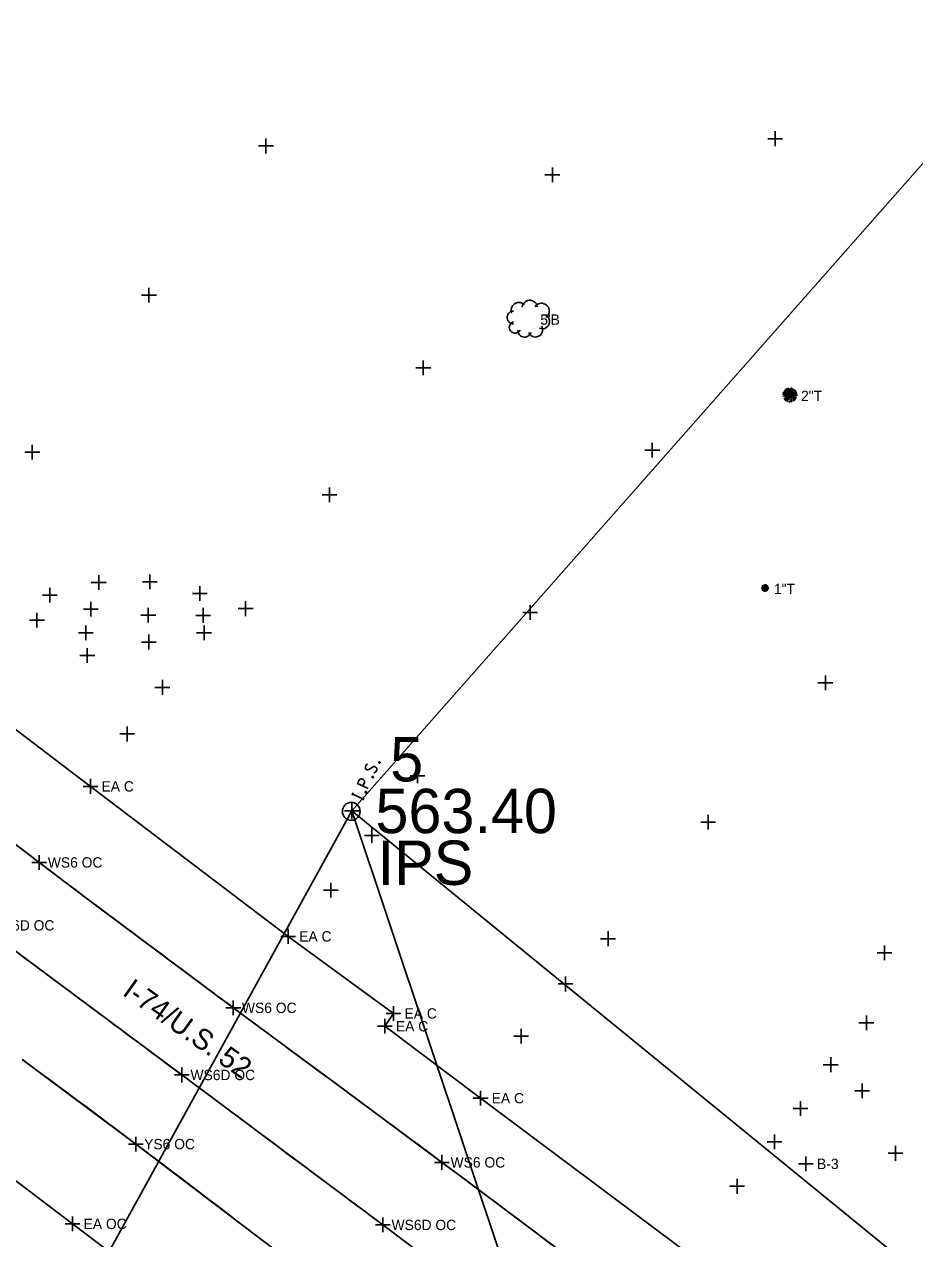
# Model space of a CAD drawing. Extents: x 1324236 to 1326110, y 459090 to 460782.
# Drawn here: x 1325040 to 1325160.4, y 460139.7 to 460303.9 of the extents above; entities that cross this region are included whole.
import ezdxf

# ---------------------------------------------------------------- set-up
doc = ezdxf.new("R2010")
doc.units = 0
for name, color, linetype in [('BD_X_Canopy', 7, 'Continuous'), ('DR_X_Ditch', 7, 'Continuous'), ('DT_X_Contour_Major', 7, 'Continuous'), ('DV_X_Property_Line', 7, 'Continuous'), ('E-RW-ODOT', 7, 'Continuous'), ('PM_X_Edge_Line', 7, 'Continuous'), ('PM_X_Lane_Line', 7, 'Continuous'), ('PV_X_Shoulder', 7, 'Continuous'), ('RD_X_Text', 7, 'Continuous'), ('RW_X_CL', 7, 'Continuous'), ('VG_X_Cells', 7, 'Continuous')]:
    doc.layers.add(name, color=color, linetype=linetype)

msp = doc.modelspace()

# ---------------------------------------------------------------- linework, layer by layer
at = {"layer": 'BD_X_Canopy'}
msp.add_lwpolyline([(1325148.74, 460096.82), (1325127.48, 460112.15), (1325127.48, 460112.15), (1325116.07, 460120.63), (1325116.07, 460120.63), (1325091.58, 460139.19), (1325091.58, 460139.19), (1325088.48, 460141.52), (1325088.48, 460141.52), (1325074.63, 460151.85), (1325074.63, 460151.85), (1325061.29, 460161.8), (1325061.29, 460161.8), (1325040.71, 460177.13), (1325040.71, 460177.13), (1325034.15, 460182.03)], dxfattribs=at)
at = {"layer": 'DR_X_Ditch'}
for points in [[(1325155.49, 460106.11), (1325134.69, 460121.41), (1325134.69, 460121.41), (1325123.41, 460129.81), (1325123.41, 460129.81), (1325098.92, 460148.15), (1325098.92, 460148.15), (1325096.46, 460149.98), (1325096.46, 460149.98), (1325083.31, 460159.73), (1325083.31, 460159.73), (1325068.25, 460170.88), (1325068.25, 460170.88), (1325049.77, 460184.67), (1325049.77, 460184.67), (1325042.01, 460190.54), (1325042.01, 460190.54), (1325032.41, 460197.89)], [(1325154.47, 460078.07), (1325145.11, 460085.02), (1325145.11, 460085.02), (1325142.61, 460086.87), (1325142.61, 460086.87), (1325114.79, 460107.64), (1325114.79, 460107.64), (1325109.8, 460111.36), (1325109.8, 460111.36), (1325095.42, 460122.04), (1325095.42, 460122.04), (1325082.31, 460131.78), (1325082.31, 460131.78), (1325070.85, 460140.45), (1325070.85, 460140.45), (1325055.08, 460152.45), (1325055.08, 460152.45), (1325039.72, 460163.87)]]:
    msp.add_lwpolyline(points, dxfattribs=at)
at = {"layer": 'DT_X_Contour_Major'}
for points in [[(1325086.41, 460203.88), (1325086.38, 460203.87), (1325086.34, 460203.85), (1325086.26, 460203.78), (1325086.19, 460203.68), (1325086.15, 460203.6), (1325086.14, 460203.57), (1325086.11, 460203.42), (1325086.13, 460203.28), (1325086.19, 460203.17), (1325086.27, 460203.11), (1325086.34, 460203.08), (1325086.44, 460203.05), (1325086.56, 460203.1), (1325087.16, 460203.49), (1325087.22, 460203.52), (1325087.28, 460203.52), (1325087.36, 460203.51), (1325087.43, 460203.48), (1325087.49, 460203.43), (1325087.53, 460203.4), (1325087.58, 460203.36), (1325087.62, 460203.32), (1325087.64, 460203.28), (1325087.66, 460203.23), (1325087.67, 460203.19), (1325087.68, 460203.14), (1325087.67, 460203.11), (1325087.64, 460203.01), (1325087.58, 460202.87), (1325087.51, 460202.79), (1325087.37, 460202.7), (1325087.27, 460202.65)], [(1325087.9, 460204.09), (1325087.93, 460204.14), (1325087.96, 460204.16), (1325088.02, 460204.17), (1325088.08, 460204.14), (1325088.11, 460204.09), (1325088.12, 460204.05), (1325088.1, 460204), (1325088.06, 460203.98), (1325088, 460203.97), (1325087.95, 460204), (1325087.91, 460204.05), (1325087.9, 460204.09)], [(1325086.5, 460200.53), (1325085.05, 460201.2), (1325085.27, 460201.68), (1325085.3, 460201.72), (1325085.36, 460201.78), (1325085.39, 460201.8), (1325085.43, 460201.82), (1325085.51, 460201.83), (1325085.58, 460201.84), (1325085.68, 460201.82), (1325085.82, 460201.75), (1325085.86, 460201.72), (1325085.92, 460201.67), (1325085.98, 460201.59), (1325085.99, 460201.54), (1325086, 460201.5), (1325086, 460201.44), (1325085.98, 460201.35), (1325085.76, 460200.87)], [(1325086.99, 460202.11), (1325087.02, 460202.16), (1325087.05, 460202.18), (1325087.11, 460202.19), (1325087.17, 460202.16), (1325087.2, 460202.11), (1325087.21, 460202.07), (1325087.19, 460202.02), (1325087.15, 460202), (1325087.09, 460201.99), (1325087.03, 460202.02), (1325087, 460202.07), (1325086.99, 460202.11)], [(1325084.32, 460199.62), (1325084.47, 460199.94)], [(1325085.85, 460199.11), (1325084.39, 460199.78)], [(1325085.77, 460198.95), (1325085.92, 460199.27)], [(1325086.05, 460200.07), (1325086.08, 460200.12), (1325086.11, 460200.14), (1325086.17, 460200.15), (1325086.23, 460200.12), (1325086.26, 460200.07), (1325086.27, 460200.03), (1325086.25, 460199.98), (1325086.21, 460199.96), (1325086.15, 460199.95), (1325086.09, 460199.98), (1325086.06, 460200.03), (1325086.05, 460200.07)]]:
    msp.add_lwpolyline(points, dxfattribs=at)
msp.add_circle((1325084.2, 460197.45), 1.2, dxfattribs=at)
at = {"layer": 'DV_X_Property_Line'}
for p, q in [((1325048.93, 460199.83), (1325048.93, 460201.83)), ((1325047.93, 460200.83), (1325049.93, 460200.83)), ((1325074.66, 460180.54), (1325076.66, 460180.54)), ((1325075.66, 460179.54), (1325075.66, 460181.54)), ((1325089.9, 460169.12), (1325089.9, 460171.12)), ((1325088.74, 460167.39), (1325088.74, 460169.39)), ((1325088.9, 460170.12), (1325090.9, 460170.12)), ((1325087.74, 460168.39), (1325089.74, 460168.39)), ((1325101.69, 460157.66), (1325101.69, 460159.66)), ((1325100.69, 460158.66), (1325102.69, 460158.66)), ((1325045.51, 460141.66), (1325047.51, 460141.66)), ((1325046.51, 460140.66), (1325046.51, 460142.66))]:
    msp.add_line(p, q, dxfattribs=at)
at = {"layer": 'E-RW-ODOT'}
for p, q in [((1325084.27, 460197.5), (1325254.99, 460391.14)), ((1325006.97, 460057.15), (1325084.27, 460197.5)), ((1325083.27, 460197.5), (1325085.27, 460197.5)), ((1325084.27, 460196.5), (1325084.27, 460198.5)), ((1325273.55, 460043.16), (1325084.27, 460197.5)), ((1325084.27, 460197.5), (1325176.95, 459920.27)), ((1325176.95, 459920.27), (1325084.27, 460197.5))]:
    msp.add_line(p, q, dxfattribs=at)
at = {"layer": 'PM_X_Edge_Line'}
for centre, radius, start, end in [((1326997.41, 462756.67), 3226.24, 232.47772, 232.69234), ((1325757.31, 461129.25), 1180.18, 232.69234, 233.16494), ((1329019.86, 465484.83), 6622.17, 233.16494, 233.364453), ((1328027.47, 464150.31), 4959.11, 233.36445, 233.5809), ((1324002.76, 458753.67), 1750.42, 53.04545, 53.67185), ((1322833.98, 457110.94), 3788.75, 53.33327, 53.5809), ((1323935.17, 458663.83), 1862.84, 52.43585, 53.04545), ((1324486.44, 459330.58), 1021.54, 53.1614, 53.33327), ((1386161.74, 541657.98), 101845.57, 233.1614025, 233.1786151), ((1325667.69, 460916.46), 978.98, 232.43585, 233.27676)]:
    msp.add_arc(centre, radius, start, end, dxfattribs=at)
at = {"layer": 'PM_X_Lane_Line'}
for centre, radius, start, end in [((1327187.22, 463060.11), 3594.31, 233.20016, 233.33064), ((1303946.52, 431845.49), 35322.04, 53.289015, 53.330639), ((1240030.72, 346130.17), 142244.2, 53.2823107, 53.2890154), ((1233447.41, 337303.65), 153255.43, 53.2758568, 53.2823163), ((1324803.59, 459759.64), 476.44, 52.8102, 53.2759)]:
    msp.add_arc(centre, radius, start, end, dxfattribs=at)
at = {"layer": 'PV_X_Shoulder'}
for points in [[(1325158.98, 460120.56), (1325156.36, 460117.88), (1325129.2, 460138.06), (1325101.69, 460158.66), (1325088.74, 460168.39), (1325089.9, 460170.12), (1325075.66, 460180.54), (1325048.93, 460200.83), (1325022.04, 460221.26), (1324994.58, 460242.45), (1324967.7, 460263.25), (1324940.22, 460284.33), (1324913.59, 460305.26), (1324886.1, 460326.42), (1324858.75, 460347.83)], [(1325146.82, 460068.18), (1325137.29, 460075.12), (1325137.29, 460075.12), (1325134.69, 460077.01), (1325134.69, 460077.01), (1325103.35, 460099.78), (1325101.71, 460100.98), (1325101.71, 460100.98), (1325084.12, 460113.57), (1325084.12, 460113.57), (1325074.34, 460120.66), (1325074.34, 460120.66), (1325068.38, 460125.12), (1325068.38, 460125.12), (1325046.51, 460141.66), (1325046.51, 460141.66), (1325023.81, 460158.87)]]:
    msp.add_lwpolyline(points, dxfattribs=at)
at = {"layer": 'RW_X_CL'}
for p, q in [((1325141.52, 460287.41), (1325141.52, 460289.41)), ((1325071.67, 460287.43), (1325073.67, 460287.43)), ((1325072.67, 460286.43), (1325072.67, 460288.43)), ((1325140.52, 460288.41), (1325142.52, 460288.41)), ((1325111.39, 460282.53), (1325111.39, 460284.53)), ((1325110.39, 460283.53), (1325112.39, 460283.53)), ((1325056.85, 460266.26), (1325056.85, 460268.26)), ((1325055.85, 460267.26), (1325057.85, 460267.26)), ((1325093.94, 460256.42), (1325093.94, 460258.42)), ((1325092.94, 460257.42), (1325094.94, 460257.42)), ((1325041.07, 460245.01), (1325041.07, 460247.01)), ((1325123.91, 460246.28), (1325125.91, 460246.28)), ((1325124.91, 460245.28), (1325124.91, 460247.28)), ((1325040.07, 460246.01), (1325042.07, 460246.01)), ((1325081.27, 460239.25), (1325081.27, 460241.25)), ((1325080.27, 460240.25), (1325082.27, 460240.25)), ((1325049.05, 460228.41), (1325051.05, 460228.41)), ((1325050.05, 460227.41), (1325050.05, 460229.41)), ((1325055.97, 460228.48), (1325057.97, 460228.48)), ((1325056.97, 460227.48), (1325056.97, 460229.48)), ((1325042.45, 460226.68), (1325044.45, 460226.68)), ((1325043.45, 460225.68), (1325043.45, 460227.68)), ((1325062.72, 460226.9), (1325064.72, 460226.9)), ((1325063.72, 460225.9), (1325063.72, 460227.9)), ((1325048.99, 460223.8), (1325048.99, 460225.8)), ((1325056.76, 460222.98), (1325056.76, 460224.98)), ((1325064.17, 460222.95), (1325064.17, 460224.95)), ((1325068.92, 460224.86), (1325070.92, 460224.86)), ((1325069.92, 460223.86), (1325069.92, 460225.86)), ((1325108.39, 460223.33), (1325108.39, 460225.33)), ((1325040.7, 460223.29), (1325042.7, 460223.29)), ((1325041.7, 460222.29), (1325041.7, 460224.29)), ((1325047.99, 460224.8), (1325049.99, 460224.8)), ((1325055.76, 460223.98), (1325057.76, 460223.98)), ((1325063.17, 460223.95), (1325065.17, 460223.95)), ((1325107.39, 460224.33), (1325109.39, 460224.33)), ((1325047.3, 460221.59), (1325049.3, 460221.59)), ((1325048.3, 460220.59), (1325048.3, 460222.59)), ((1325063.29, 460221.6), (1325065.29, 460221.6)), ((1325064.29, 460220.6), (1325064.29, 460222.6)), ((1325055.82, 460220.35), (1325057.82, 460220.35)), ((1325056.82, 460219.35), (1325056.82, 460221.35)), ((1325047.51, 460218.53), (1325049.51, 460218.53)), ((1325048.51, 460217.53), (1325048.51, 460219.53)), ((1325058.66, 460213.22), (1325058.66, 460215.22)), ((1325148.31, 460213.82), (1325148.31, 460215.82)), ((1325057.66, 460214.22), (1325059.66, 460214.22)), ((1325147.31, 460214.82), (1325149.31, 460214.82)), ((1325053.89, 460206.91), (1325053.89, 460208.91)), ((1325052.89, 460207.91), (1325054.89, 460207.91)), ((1325092.15, 460202.26), (1325094.15, 460202.26)), ((1325093.15, 460201.26), (1325093.15, 460203.26)), ((1325132.46, 460195), (1325132.46, 460197)), ((1325131.46, 460196), (1325133.46, 460196)), ((1325085.99, 460194.18), (1325087.99, 460194.18)), ((1325086.99, 460193.18), (1325086.99, 460195.18)), ((1325041.01, 460190.54), (1325043.01, 460190.54)), ((1325042.01, 460189.54), (1325042.01, 460191.54)), ((1325081.43, 460185.79), (1325081.43, 460187.79)), ((1325080.43, 460186.79), (1325082.43, 460186.79)), ((1325118.92, 460179.23), (1325118.92, 460181.23)), ((1325117.92, 460180.23), (1325119.92, 460180.23)), ((1325156.29, 460177.33), (1325156.29, 460179.33)), ((1325155.29, 460178.33), (1325157.29, 460178.33)), ((1325112.18, 460174.11), (1325114.18, 460174.11)), ((1325113.18, 460173.11), (1325113.18, 460175.11)), ((1325067.25, 460170.88), (1325069.25, 460170.88)), ((1325068.25, 460169.88), (1325068.25, 460171.88)), ((1325153.85, 460167.86), (1325153.85, 460169.86)), ((1325107.17, 460166.06), (1325107.17, 460168.06)), ((1325152.85, 460168.86), (1325154.85, 460168.86)), ((1325106.17, 460167.06), (1325108.17, 460167.06)), ((1325149.03, 460162.19), (1325149.03, 460164.19)), ((1325061.29, 460160.8), (1325061.29, 460162.8)), ((1325148.03, 460163.19), (1325150.03, 460163.19)), ((1325060.29, 460161.8), (1325062.29, 460161.8)), ((1325152.28, 460159.65), (1325154.28, 460159.65)), ((1325153.28, 460158.65), (1325153.28, 460160.65)), ((1325144.95, 460156.27), (1325144.95, 460158.27)), ((1325143.95, 460157.27), (1325145.95, 460157.27)), ((1325055.08, 460151.45), (1325055.08, 460153.45)), ((1325140.44, 460152.77), (1325142.44, 460152.77)), ((1325141.44, 460151.77), (1325141.44, 460153.77)), ((1325054.08, 460152.45), (1325056.08, 460152.45)), ((1325096.46, 460148.98), (1325096.46, 460150.98)), ((1325156.8, 460151.21), (1325158.8, 460151.21)), ((1325157.8, 460150.21), (1325157.8, 460152.21)), ((1325095.46, 460149.98), (1325097.46, 460149.98)), ((1325144.68, 460149.78), (1325146.68, 460149.78)), ((1325145.68, 460148.78), (1325145.68, 460150.78)), ((1325136.37, 460145.74), (1325136.37, 460147.74)), ((1325135.37, 460146.74), (1325137.37, 460146.74)), ((1325087.48, 460141.52), (1325089.48, 460141.52)), ((1325088.48, 460140.52), (1325088.48, 460142.52))]:
    msp.add_line(p, q, dxfattribs=at)
at = {"layer": 'VG_X_Cells'}
for p, q in [((1325143.52, 460253.76), (1325142.73, 460254.4)), ((1325143.16, 460254.21), (1325142.91, 460254.51)), ((1325143.52, 460253.76), (1325142.96, 460254.61)), ((1325143.36, 460254.14), (1325143.21, 460254.48)), ((1325143.52, 460253.76), (1325143.25, 460254.74)), ((1325143.52, 460253.76), (1325143.67, 460254.76)), ((1325143.52, 460254.18), (1325143.52, 460254.65)), ((1325143.72, 460254.29), (1325143.86, 460254.67)), ((1325143.72, 460254.29), (1325143.86, 460254.67)), ((1325143.74, 460254.1), (1325143.95, 460254.41)), ((1325144.03, 460254.41), (1325144.15, 460254.55)), ((1325144.07, 460254.28), (1325144.22, 460254.45)), ((1325142.86, 460253.83), (1325142.51, 460253.87)), ((1325142.95, 460253.68), (1325142.56, 460253.61)), ((1325143.52, 460253.76), (1325142.57, 460254.12)), ((1325142.79, 460253.99), (1325142.57, 460254.03)), ((1325143.1, 460253.77), (1325142.63, 460253.76)), ((1325143.52, 460253.76), (1325142.67, 460253.21)), ((1325143.16, 460253.98), (1325142.75, 460254.21)), ((1325143.07, 460253.41), (1325142.77, 460253.15)), ((1325143.18, 460253.65), (1325142.79, 460253.52)), ((1325143.52, 460253.76), (1325142.88, 460252.97)), ((1325143.28, 460253.5), (1325143.01, 460253.19)), ((1325143.35, 460253.75), (1325143.04, 460253.71)), ((1325143.17, 460253.09), (1325143.06, 460252.87)), ((1325143.52, 460253.76), (1325143.16, 460253.8)), ((1325143.52, 460253.76), (1325143.16, 460252.82)), ((1325143.48, 460252.96), (1325143.46, 460252.76)), ((1325143.52, 460253.76), (1325143.49, 460253.14)), ((1325143.52, 460253.76), (1325144.36, 460254.32)), ((1325143.52, 460253.76), (1325143.84, 460254.16)), ((1325143.52, 460253.76), (1325144.49, 460254.03)), ((1325143.52, 460253.76), (1325143.61, 460253.41)), ((1325143.52, 460253.76), (1325143.77, 460253.37)), ((1325143.52, 460253.76), (1325144.31, 460253.13)), ((1325143.52, 460253.76), (1325144.46, 460253.41)), ((1325143.52, 460253.76), (1325143.97, 460253.69)), ((1325143.58, 460253.91), (1325143.71, 460254.2)), ((1325143.6, 460253.01), (1325143.65, 460252.79)), ((1325143.65, 460253.28), (1325143.78, 460252.79)), ((1325143.87, 460253.32), (1325144.13, 460253.01)), ((1325143.93, 460253.13), (1325144.07, 460252.92)), ((1325143.95, 460253.74), (1325144.53, 460253.72)), ((1325144.08, 460253.85), (1325144.47, 460253.92)), ((1325144.19, 460254.11), (1325144.4, 460254.23)), ((1325144.19, 460253.42), (1325144.41, 460253.31)), ((1325140.15, 460227.65), (1325140.02, 460228.14)), ((1325140.15, 460227.65), (1325140.23, 460228.15)), ((1325140.15, 460227.86), (1325140.15, 460228.1)), ((1325140.25, 460227.92), (1325140.32, 460228.11)), ((1325140.25, 460227.92), (1325140.32, 460228.11)), ((1325139.82, 460227.69), (1325139.65, 460227.71)), ((1325139.79, 460227.77), (1325139.67, 460227.79)), ((1325139.87, 460227.61), (1325139.67, 460227.58)), ((1325140.15, 460227.65), (1325139.68, 460227.83)), ((1325139.94, 460227.66), (1325139.7, 460227.65)), ((1325140.15, 460227.65), (1325139.73, 460227.38)), ((1325140.15, 460227.65), (1325139.75, 460227.97)), ((1325139.97, 460227.76), (1325139.76, 460227.88)), ((1325139.93, 460227.48), (1325139.77, 460227.35)), ((1325139.98, 460227.6), (1325139.79, 460227.53)), ((1325140.15, 460227.65), (1325139.83, 460227.26)), ((1325139.97, 460227.88), (1325139.84, 460228.03)), ((1325140.15, 460227.65), (1325139.87, 460228.08)), ((1325140.03, 460227.52), (1325139.9, 460227.37)), ((1325140.07, 460227.65), (1325139.91, 460227.63)), ((1325139.97, 460227.32), (1325139.92, 460227.21)), ((1325140.15, 460227.65), (1325139.97, 460227.67)), ((1325140.15, 460227.65), (1325139.97, 460227.18)), ((1325140.07, 460227.84), (1325140, 460228.01)), ((1325140.13, 460227.25), (1325140.12, 460227.15)), ((1325140.15, 460227.65), (1325140.13, 460227.34)), ((1325140.15, 460227.65), (1325140.57, 460227.93)), ((1325140.15, 460227.65), (1325140.31, 460227.85)), ((1325140.15, 460227.65), (1325140.64, 460227.79)), ((1325140.15, 460227.65), (1325140.2, 460227.48)), ((1325140.15, 460227.65), (1325140.28, 460227.46)), ((1325140.15, 460227.65), (1325140.54, 460227.34)), ((1325140.15, 460227.65), (1325140.62, 460227.48)), ((1325140.15, 460227.65), (1325140.38, 460227.62)), ((1325140.18, 460227.73), (1325140.24, 460227.87)), ((1325140.19, 460227.28), (1325140.21, 460227.17)), ((1325140.22, 460227.41), (1325140.28, 460227.17)), ((1325140.26, 460227.82), (1325140.36, 460227.98)), ((1325140.33, 460227.43), (1325140.45, 460227.28)), ((1325140.36, 460227.34), (1325140.43, 460227.23)), ((1325140.37, 460227.64), (1325140.65, 460227.63)), ((1325140.41, 460227.98), (1325140.46, 460228.05)), ((1325140.43, 460227.91), (1325140.5, 460228)), ((1325140.43, 460227.7), (1325140.63, 460227.73)), ((1325140.48, 460227.83), (1325140.59, 460227.89)), ((1325140.49, 460227.48), (1325140.6, 460227.43))]:
    msp.add_line(p, q, dxfattribs=at)
for points in [[(1325107.61, 460265.98), (1325107.45, 460266.1), (1325107.26, 460266.19), (1325107.07, 460266.25), (1325106.86, 460266.26), (1325106.66, 460266.24), (1325106.47, 460266.18), (1325106.29, 460266.08), (1325106.13, 460265.95), (1325106, 460265.8), (1325105.9, 460265.62), (1325105.83, 460265.42), (1325105.81, 460265.22), (1325105.82, 460265.02), (1325105.87, 460264.82)], [(1325109.35, 460265.69), (1325109.31, 460265.88), (1325109.23, 460266.06), (1325109.11, 460266.22), (1325108.97, 460266.35), (1325108.81, 460266.46), (1325108.63, 460266.53), (1325108.43, 460266.57), (1325108.24, 460266.57), (1325108.05, 460266.53), (1325107.87, 460266.46), (1325107.7, 460266.35), (1325107.56, 460266.22), (1325107.45, 460266.06), (1325107.37, 460265.88), (1325107.32, 460265.69)], [(1325110.51, 460264.24), (1325110.66, 460264.36), (1325110.79, 460264.51), (1325110.89, 460264.68), (1325110.95, 460264.86), (1325110.98, 460265.06), (1325110.97, 460265.25), (1325110.93, 460265.44), (1325110.85, 460265.62), (1325110.74, 460265.78), (1325110.6, 460265.92), (1325110.44, 460266.03), (1325110.26, 460266.1), (1325110.07, 460266.15), (1325109.88, 460266.16), (1325109.69, 460266.13), (1325109.5, 460266.07), (1325109.33, 460265.97), (1325109.18, 460265.84), (1325109.06, 460265.69)], [(1325106.16, 460265.11), (1325106, 460265.1), (1325105.85, 460265.05), (1325105.7, 460264.98), (1325105.57, 460264.88), (1325105.46, 460264.77), (1325105.38, 460264.63), (1325105.32, 460264.48), (1325105.29, 460264.32), (1325105.29, 460264.16), (1325105.32, 460264), (1325105.38, 460263.85), (1325105.46, 460263.72), (1325105.57, 460263.6), (1325105.7, 460263.5), (1325105.85, 460263.43), (1325106, 460263.38), (1325106.16, 460263.37)], [(1325109.64, 460262.79), (1325109.82, 460262.73), (1325110, 460262.71), (1325110.19, 460262.72), (1325110.37, 460262.76), (1325110.53, 460262.84), (1325110.68, 460262.95), (1325110.81, 460263.09), (1325110.91, 460263.25), (1325110.98, 460263.42), (1325111.01, 460263.6), (1325111.01, 460263.79), (1325110.97, 460263.97), (1325110.9, 460264.14), (1325110.8, 460264.29), (1325110.67, 460264.43), (1325110.51, 460264.53)], [(1325106.16, 460263.66), (1325106.02, 460263.61), (1325105.88, 460263.53), (1325105.77, 460263.42), (1325105.68, 460263.3), (1325105.62, 460263.16), (1325105.58, 460263.01), (1325105.57, 460262.86), (1325105.6, 460262.71), (1325105.65, 460262.56), (1325105.73, 460262.43), (1325105.83, 460262.32), (1325105.96, 460262.23), (1325106.1, 460262.16), (1325106.24, 460262.12), (1325106.4, 460262.12), (1325106.55, 460262.14), (1325106.69, 460262.19), (1325106.83, 460262.27), (1325106.94, 460262.38), (1325107.03, 460262.5)], [(1325108.19, 460262.21), (1325108.28, 460262.04), (1325108.4, 460261.89), (1325108.54, 460261.77), (1325108.71, 460261.68), (1325108.89, 460261.62), (1325109.08, 460261.59), (1325109.27, 460261.61), (1325109.45, 460261.66), (1325109.62, 460261.74), (1325109.77, 460261.86), (1325109.89, 460262), (1325109.99, 460262.17), (1325110.05, 460262.35), (1325110.07, 460262.54), (1325110.06, 460262.73), (1325110.02, 460262.91), (1325109.93, 460263.08)], [(1325106.74, 460262.5), (1325106.75, 460262.33), (1325106.79, 460262.16), (1325106.86, 460262.01), (1325106.97, 460261.87), (1325107.09, 460261.75), (1325107.24, 460261.66), (1325107.4, 460261.6), (1325107.57, 460261.58), (1325107.74, 460261.58), (1325107.91, 460261.62), (1325108.06, 460261.69), (1325108.2, 460261.78), (1325108.32, 460261.91), (1325108.42, 460262.05), (1325108.48, 460262.21)]]:
    msp.add_lwpolyline(points, dxfattribs=at)

# ---------------------------------------------------------------- texts
at = {"layer": 'DV_X_Property_Line'}
for s, p in [('EA C', (1325050.43, 460200.13)), ('EA C', (1325077.16, 460179.84)), ('EA C', (1325091.4, 460169.42)), ('EA C', (1325090.24, 460167.69)), ('EA C', (1325103.19, 460157.96)), ('EA OC', (1325048.01, 460140.96))]:
    msp.add_text(s, height=1.4, dxfattribs=at).set_placement(p)
at = {"layer": 'E-RW-ODOT'}
for s, p in [('5', (1325089.47, 460201.5)), ('563.40', (1325087.47, 460194.5)), ('IPS', (1325087.77, 460187.5))]:
    msp.add_text(s, height=6, dxfattribs=at).set_placement(p)
at = {"layer": 'RD_X_Text'}
msp.add_text('I-74/U.S. 52 ', height=2.8, rotation=324.7532, dxfattribs=at).set_placement((1325053.13, 460172.71))
at = {"layer": 'RW_X_CL'}
for s, p in [('WS6 OC', (1325043.17, 460189.84)), ('WS6D OC', (1325035.32, 460181.33)), ('WS6 OC', (1325069.42, 460170.18)), ('WS6D OC', (1325062.46, 460161.1)), ('YS6 OC', (1325056.2, 460151.75)), ('WS6 OC', (1325097.63, 460149.28)), ('B-3', (1325147.18, 460149.08)), ('WS6D OC', (1325089.65, 460140.82))]:
    msp.add_text(s, height=1.4, dxfattribs=at).set_placement(p)
at = {"layer": 'VG_X_Cells'}
for s, p in [("5'B", (1325109.76, 460263.25)), ('2"T', (1325145.02, 460252.93)), ('1"T', (1325141.35, 460226.82))]:
    msp.add_text(s, height=1.4, dxfattribs=at).set_placement(p)

doc.saveas('drawing.dxf')
